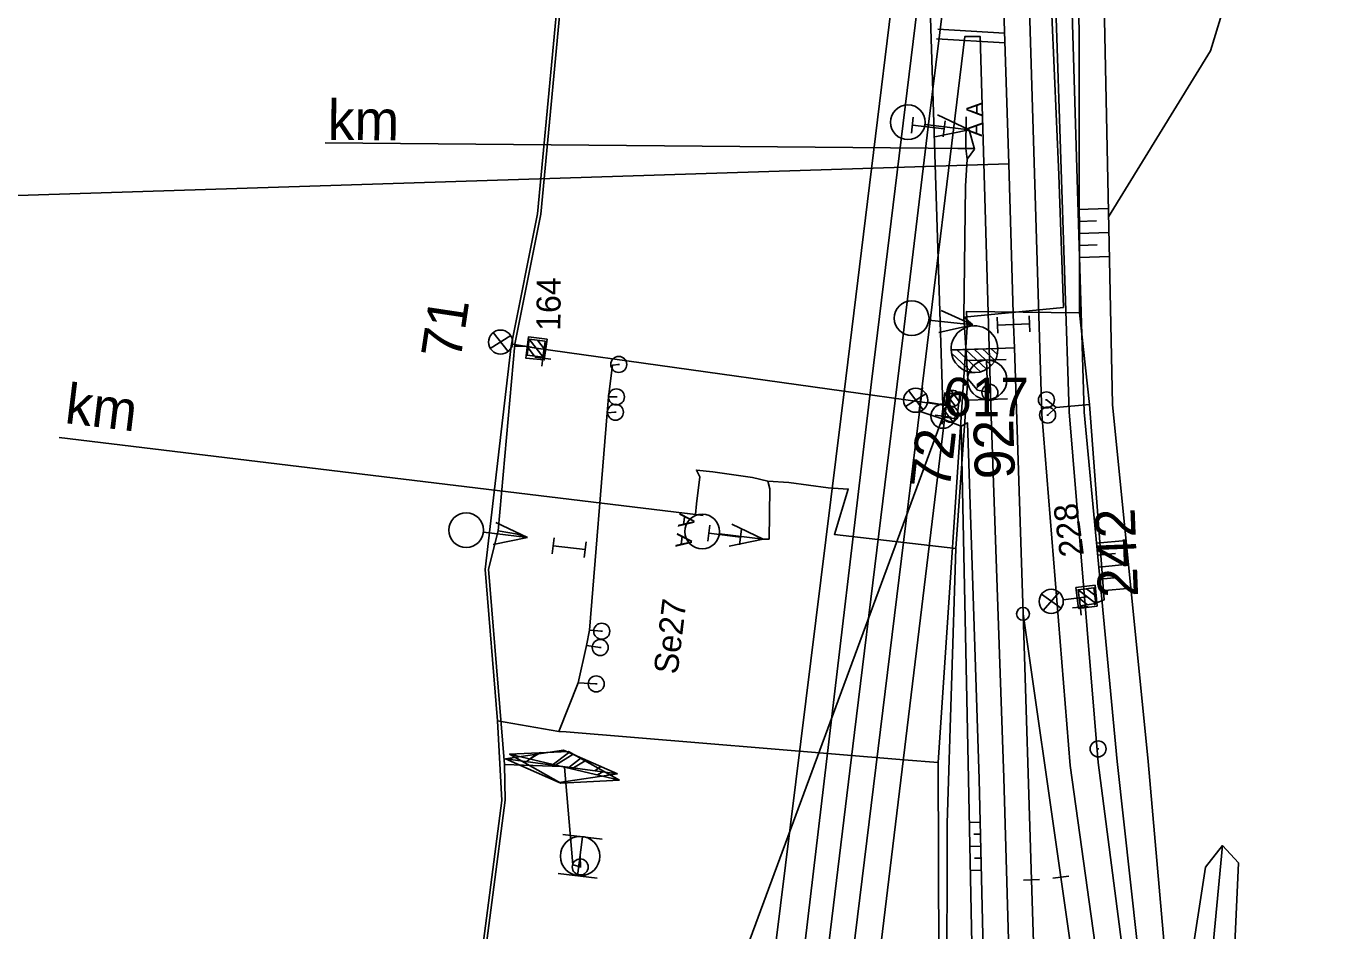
# Model space of a CAD drawing. Extents: x -598638 to -597933, y -1164002 to -1161904.
# Drawn here: x -598566.1 to -598484.7, y -1163411 to -1163354.5 of the extents above; entities that cross this region are included whole.
import ezdxf

# ---------------------------------------------------------------- set-up
doc = ezdxf.new("R2010")
doc.units = 0
for name, color, linetype in [('Vrstva 1', 7, 'Continuous'), ('Vrstva 11', 7, 'Continuous'), ('Vrstva 12', 7, 'Continuous'), ('Vrstva 13', 7, 'Continuous'), ('Vrstva 2', 7, 'Continuous'), ('Vrstva 25', 7, 'Continuous'), ('Vrstva 26', 7, 'Continuous'), ('Vrstva 28', 7, 'Continuous'), ('Vrstva 3', 7, 'Continuous'), ('Vrstva 31', 7, 'Continuous'), ('Vrstva 35', 7, 'Continuous'), ('Vrstva 4', 7, 'Continuous'), ('Vrstva 48', 7, 'Continuous'), ('Vrstva 49', 7, 'Continuous'), ('Vrstva 51', 7, 'Continuous'), ('Vrstva 6', 7, 'Continuous'), ('Vrstva 63', 7, 'Continuous'), ('Vrstva 7', 7, 'Continuous')]:
    doc.layers.add(name, color=color, linetype=linetype)

msp = doc.modelspace()

# ---------------------------------------------------------------- linework, layer by layer
at = {"layer": 'Vrstva 1'}
msp.add_line((-598504.722, -1163363.13), (-598604.671, -1163366.323), dxfattribs=at)
for points in [[(-598540.061, -1163609.51), (-598538.55, -1163597.18), (-598535.661, -1163573.393), (-598532.502, -1163547.551), (-598529.47, -1163522.734), (-598526.451, -1163497.915), (-598523.419, -1163473.102), (-598521.347, -1163456.074), (-598520.4, -1163448.28), (-598517.374, -1163423.469), (-598514.348, -1163398.653), (-598511.323, -1163373.834), (-598509.75, -1163360.838), (-598508.294, -1163349.021), (-598507.057, -1163338.802)], [(-598504.357, -1163374.632), (-598504.42, -1163373.167), (-598504.722, -1163363.13), (-598505.089, -1163351.642)], [(-598503.303, -1163407.847), (-598503.83, -1163391.239), (-598504.357, -1163374.632)], [(-598501.472, -1163407.683), (-598503.83, -1163391.239)], [(-598502.896, -1163420.949), (-598503.303, -1163407.847)], [(-598499.762, -1163419.602), (-598501.472, -1163407.683)]]:
    msp.add_lwpolyline(points, dxfattribs=at)
at = {"layer": 'Vrstva 11'}
for p, q in [((-598534.327, -1163375.142), (-598534.73, -1163374.619)), ((-598533.801, -1163375.209), (-598534.662, -1163374.093)), ((-598533.731, -1163374.687), (-598534.139, -1163374.158)), ((-598508.658, -1163377.504), (-598508.077, -1163378.253)), ((-598508.345, -1163377.295), (-598507.798, -1163378)), ((-598508.785, -1163378.499), (-598508.205, -1163379.246)), ((-598508.473, -1163378.289), (-598507.924, -1163378.996)), ((-598499.283, -1163390.602), (-598500.4, -1163389.741)), ((-598499.809, -1163390.67), (-598500.332, -1163390.267)), ((-598499.348, -1163390.079), (-598499.877, -1163389.671))]:
    msp.add_line(p, q, dxfattribs=at)
for points in [[(-598534.79, -1163375.082), (-598534.662, -1163374.09), (-598533.67, -1163374.218), (-598533.798, -1163375.21)], [(-598500.272, -1163390.73), (-598500.4, -1163389.738), (-598499.408, -1163389.61), (-598499.28, -1163390.602)]]:
    msp.add_lwpolyline(points, close=True, dxfattribs=at)
for points in [[(-598534.79, -1163375.082), (-598534.662, -1163374.09), (-598533.67, -1163374.218), (-598533.798, -1163375.21), (-598534.79, -1163375.082)], [(-598534.23, -1163374.65), (-598508.31, -1163378.28)], [(-598500.272, -1163390.73), (-598500.4, -1163389.738), (-598499.408, -1163389.61), (-598499.28, -1163390.602), (-598500.272, -1163390.73)]]:
    msp.add_lwpolyline(points, dxfattribs=at)
for centre in [(-598508.248, -1163377.784), (-598508.248, -1163377.784), (-598508.372, -1163378.776), (-598508.372, -1163378.776)]:
    msp.add_circle(centre, 0.5, dxfattribs=at)
at = {"layer": 'Vrstva 12'}
for p, q in [((-598499.32, -1163389.44), (-598499.2, -1163390.75)), ((-598500.53, -1163389.6), (-598500.36, -1163390.9)), ((-598499.2, -1163390.75), (-598500.36, -1163390.9))]:
    msp.add_line(p, q, dxfattribs=at)
for points in [[(-598533.55, -1163374.08), (-598533.72, -1163375.38), (-598534.88, -1163375.27), (-598534.71, -1163373.95), (-598533.55, -1163374.08)], [(-598508.9, -1163378.94), (-598508.71, -1163377.43), (-598507.77, -1163377.55), (-598507.96, -1163379.06), (-598508.9, -1163378.94)], [(-598500.53, -1163389.6), (-598499.32, -1163389.44)]]:
    msp.add_lwpolyline(points, dxfattribs=at)
at = {"layer": 'Vrstva 13'}
for points in [[(-598494.35, -1163419.483), (-598496.011, -1163400.454), (-598498.249, -1163378.174), (-598498.761, -1163353.124), (-598499.609, -1163337.312), (-598498.929, -1163312.944), (-598495.877, -1163288.306), (-598493.588, -1163272.056)], [(-598496.865, -1163550.379), (-598493.505, -1163528.163), (-598490.621, -1163501.64), (-598489.924, -1163482.727), (-598490.976, -1163458.949), (-598491.652, -1163439.005), (-598492.756, -1163420.248), (-598491.376, -1163405.706)]]:
    msp.add_lwpolyline(points, dxfattribs=at)
at = {"layer": 'Vrstva 2'}
for p, q in [((-598508.321, -1163374.76), (-598505.395, -1163374.668)), ((-598508.321, -1163374.761), (-598508.321, -1163374.76)), ((-598508.318, -1163374.769), (-598504.357, -1163374.632)), ((-598506.495, -1163376.128), (-598507.964, -1163374.748)), ((-598506.11, -1163375.968), (-598507.427, -1163374.731)), ((-598505.809, -1163375.729), (-598506.89, -1163374.714)), ((-598505.581, -1163375.423), (-598506.353, -1163374.698)), ((-598505.434, -1163375.039), (-598505.815, -1163374.681)), ((-598507.008, -1163376.168), (-598508.299, -1163374.956)), ((-598503.803, -1163407.863), (-598502.803, -1163407.831)), ((-598501.967, -1163407.754), (-598500.977, -1163407.612))]:
    msp.add_line(p, q, dxfattribs=at)
for points in [[(-598503.303, -1163407.847), (-598503.83, -1163391.239), (-598504.357, -1163374.632)], [(-598501.472, -1163407.683), (-598503.83, -1163391.239)]]:
    msp.add_lwpolyline(points, dxfattribs=at)
msp.add_circle((-598503.836, -1163391.239), 0.4, dxfattribs=at)
for centre, radius, start, end in [((-598506.863, -1163374.714), 1.462, 1.74804, 182.21756), ((-598506.863, -1163374.715), 1.464, 181.83757, 1.79842)]:
    msp.add_arc(centre, radius, start, end, dxfattribs=at)
at = {"layer": 'Vrstva 25'}
for p, q in [((-598537.092, -1163374.668), (-598535.815, -1163373.868)), ((-598536.907, -1163373.67), (-598535.985, -1163374.864)), ((-598535.709, -1163374.399), (-598534.23, -1163374.65)), ((-598529.122, -1163375.664), (-598529.022, -1163375.664)), ((-598529.271, -1163377.692), (-598529.171, -1163377.692)), ((-598511.172, -1163378.298), (-598509.895, -1163377.498)), ((-598510.987, -1163377.3), (-598510.065, -1163378.494)), ((-598509.789, -1163378.029), (-598508.31, -1163378.28)), ((-598505.95, -1163377.41), (-598505.85, -1163377.41)), ((-598502.419, -1163377.879), (-598502.319, -1163377.879)), ((-598529.331, -1163378.646), (-598529.231, -1163378.646)), ((-598502.346, -1163378.825), (-598502.246, -1163378.825)), ((-598502.687, -1163390.019), (-598501.455, -1163390.89)), ((-598502.571, -1163391.027), (-598501.584, -1163389.888)), ((-598501.327, -1163390.364), (-598499.84, -1163390.17)), ((-598530.187, -1163392.327), (-598530.087, -1163392.327)), ((-598530.279, -1163393.34), (-598530.179, -1163393.34)), ((-598530.531, -1163395.616), (-598530.431, -1163395.616)), ((-598531.52, -1163407.04), (-598531.42, -1163407.04))]:
    msp.add_line(p, q, dxfattribs=at)
for centre, radius in [((-598536.452, -1163374.271), 0.754), ((-598529.072, -1163375.664), 0.5), ((-598529.221, -1163377.692), 0.5), ((-598510.532, -1163377.901), 0.754), ((-598505.899, -1163377.416), 0.5), ((-598502.369, -1163377.879), 0.5), ((-598529.281, -1163378.646), 0.5), ((-598502.296, -1163378.825), 0.5), ((-598502.075, -1163390.46), 0.754), ((-598530.137, -1163392.327), 0.5), ((-598530.229, -1163393.34), 0.5), ((-598530.481, -1163395.616), 0.5), ((-598531.478, -1163407.046), 0.5)]:
    msp.add_circle(centre, radius, dxfattribs=at)
at = {"layer": 'Vrstva 26'}
for points in [[(-598498.151, -1163310.108), (-598499.599, -1163328.429), (-598500.358, -1163348.412), (-598500.307, -1163372.443), (-598499.677, -1163378.168), (-598498.772, -1163390.367), (-598499.181, -1163390.54), (-598499.381, -1163390.672)], [(-598537.412, -1163388.462), (-598535.789, -1163374.512), (-598534.155, -1163366.253), (-598531.883, -1163342.146), (-598532.145, -1163325.87), (-598528.971, -1163314.666)], [(-598507.316, -1163373.338), (-598507.371, -1163372.367), (-598500.307, -1163372.443)], [(-598507.316, -1163373.338), (-598509.135, -1163400.512)], [(-598535.533, -1163374.519), (-598534.909, -1163374.528), (-598534.527, -1163374.59)], [(-598532.805, -1163398.581), (-598531.604, -1163395.54), (-598531.09, -1163393.218), (-598530.889, -1163392.255), (-598529.802, -1163378.681), (-598529.704, -1163377.682), (-598529.471, -1163375.716), (-598529.072, -1163375.664)], [(-598529.704, -1163377.682), (-598529.221, -1163377.692)], [(-598501.756, -1163378.345), (-598502.369, -1163377.879)], [(-598529.802, -1163378.681), (-598529.281, -1163378.646)], [(-598499.677, -1163378.168), (-598501.756, -1163378.345), (-598502.296, -1163378.825)], [(-598545.332, -1163489.631), (-598545.008, -1163488.013), (-598544.032, -1163482.82), (-598544.736, -1163479.954), (-598543.755, -1163474.998), (-598543.294, -1163474.254), (-598542.12, -1163472.372), (-598541.435, -1163468.483), (-598542.191, -1163467.82), (-598543.3, -1163466.865), (-598549.702, -1163463.438), (-598550.312, -1163461.998), (-598547.972, -1163456.485), (-598545.109, -1163451.121), (-598540.175, -1163430.965), (-598539.287, -1163425.257), (-598536.381, -1163402.898), (-598536.647, -1163397.91), (-598537.412, -1163388.462)], [(-598530.889, -1163392.255), (-598530.137, -1163392.327)], [(-598531.09, -1163393.218), (-598530.229, -1163393.34)], [(-598531.604, -1163395.54), (-598530.481, -1163395.616)], [(-598509.054, -1163424.983), (-598509.135, -1163400.512), (-598511.269, -1163400.35), (-598532.35, -1163398.602), (-598532.805, -1163398.581), (-598536.647, -1163397.91)]]:
    msp.add_lwpolyline(points, dxfattribs=at)
at = {"layer": 'Vrstva 28'}
for points in [[(-598507.52, -1163372.71), (-598501.31, -1163372.1), (-598501.6, -1163363.82), (-598502.03, -1163353.84), (-598501.69, -1163351.72), (-598500.63, -1163349.09), (-598500.75, -1163347.83), (-598501.57, -1163344.03), (-598502, -1163332.02), (-598501.94, -1163329.98), (-598501.12, -1163326.18), (-598499.72, -1163322.54), (-598499.97, -1163317.56), (-598499.92, -1163312.46), (-598499.63, -1163308.85), (-598499.29, -1163304.55), (-598499.04, -1163301.37), (-598499.81, -1163300.75), (-598504.99, -1163300.1), (-598505.15, -1163303.01), (-598505.18, -1163303.79)], [(-598528.804, -1163314.884), (-598530.72, -1163322.93), (-598531.923, -1163325.895), (-598531.661, -1163342.171), (-598533.933, -1163366.278), (-598535.552, -1163374.399), (-598536.6, -1163386.06), (-598535.39, -1163386.27), (-598534.78, -1163386.47)], [(-598514.7, -1163462.74), (-598512.83, -1163458.19), (-598512.34, -1163456.24), (-598510.26, -1163440.38), (-598509.64, -1163435.49), (-598509.26, -1163430.59), (-598508.84, -1163423.22), (-598508.68, -1163420.47), (-598508.59, -1163415.6), (-598508.57, -1163404.31), (-598508.02, -1163387.15), (-598507.28, -1163376.57), (-598507.52, -1163372.71), (-598507.43, -1163364.54), (-598507.33, -1163362.84), (-598506.87, -1163362.23), (-598507.2, -1163361.02)], [(-598507.33, -1163362.84), (-598507.4, -1163362.18)], [(-598507.52, -1163372.71), (-598506.96, -1163373.2)], [(-598507.28, -1163376.57), (-598506.67, -1163377.27), (-598505.9, -1163377.41), (-598506.07, -1163376.62)], [(-598508.02, -1163387.15), (-598515.61, -1163386.28), (-598514.74, -1163383.45), (-598515.99, -1163383.38), (-598518.45, -1163383.04), (-598519.76, -1163382.96), (-598520.73, -1163382.72), (-598523.2, -1163382.38), (-598524.22, -1163382.26), (-598524.01, -1163382.69), (-598524.21, -1163384.36), (-598524.29, -1163385.04)], [(-598519.76, -1163382.96), (-598519.63, -1163383.44), (-598519.69, -1163386.57), (-598520.05, -1163386.57)], [(-598536.6, -1163386.06), (-598537.199, -1163388.446), (-598536.213, -1163400.645), (-598532.653, -1163400.768), (-598532.455, -1163400.815), (-598531.93, -1163406.91), (-598531.47, -1163407.04), (-598531.49, -1163406.38)], [(-598536.213, -1163400.645), (-598536.168, -1163402.882), (-598539.241, -1163426.522), (-598539.962, -1163430.949), (-598541.59, -1163438.158), (-598542.388, -1163441.691), (-598544.896, -1163451.105), (-598547.759, -1163456.469), (-598550.099, -1163461.982), (-598549.524, -1163463.34), (-598543.087, -1163466.786), (-598541.213, -1163468.412), (-598540.83, -1163467.6), (-598540.45, -1163467.34), (-598539.56, -1163463.45), (-598538.42, -1163453.46), (-598538.38, -1163452.75)]]:
    msp.add_lwpolyline(points, dxfattribs=at)
at = {"layer": 'Vrstva 3'}
for p, q in [((-598507.2, -1163361.02), (-598509.17, -1163360.082)), ((-598510.803, -1163361.213), (-598510.682, -1163360.22)), ((-598510.743, -1163360.717), (-598508.757, -1163360.959)), ((-598507.2, -1163361.02), (-598509.939, -1163360.682)), ((-598508.818, -1163361.456), (-598508.697, -1163360.463)), ((-598507.2, -1163361.02), (-598509.339, -1163361.452)), ((-598506.96, -1163373.2), (-598508.944, -1163372.292)), ((-598506.96, -1163373.2), (-598509.704, -1163372.903)), ((-598506.96, -1163373.2), (-598509.092, -1163373.664)), ((-598505.401, -1163373.703), (-598505.438, -1163372.704)), ((-598505.419, -1163373.204), (-598503.421, -1163373.13)), ((-598503.402, -1163373.63), (-598503.439, -1163372.631)), ((-598507.34, -1163375.428), (-598504.878, -1163375.35)), ((-598506.031, -1163377.851), (-598506.109, -1163375.389)), ((-598507.262, -1163377.89), (-598504.8, -1163377.812)), ((-598534.78, -1163386.47), (-598537.52, -1163386.136)), ((-598534.78, -1163386.47), (-598536.751, -1163385.535)), ((-598523.513, -1163386.695), (-598523.392, -1163385.703)), ((-598523.453, -1163386.199), (-598521.467, -1163386.441)), ((-598520.05, -1163386.57), (-598522.021, -1163385.635)), ((-598521.528, -1163386.937), (-598521.407, -1163385.945)), ((-598534.78, -1163386.47), (-598536.918, -1163386.904)), ((-598533.223, -1163387.485), (-598533.102, -1163386.493)), ((-598533.163, -1163386.989), (-598531.177, -1163387.231)), ((-598531.238, -1163387.727), (-598531.117, -1163386.735)), ((-598520.05, -1163386.57), (-598522.79, -1163386.236)), ((-598520.05, -1163386.57), (-598522.188, -1163387.004)), ((-598532.564, -1163405.008), (-598530.118, -1163405.306)), ((-598531.639, -1163407.603), (-598531.341, -1163405.157)), ((-598532.862, -1163407.454), (-598530.416, -1163407.752))]:
    msp.add_line(p, q, dxfattribs=at)
for centre, radius in [((-598511.018, -1163360.544), 1.084), ((-598510.786, -1163372.78), 1.084), ((-598506.068, -1163376.618), 1.232), ((-598538.598, -1163386.012), 1.084), ((-598523.86, -1163386.101), 1.084), ((-598531.485, -1163406.369), 1.232)]:
    msp.add_circle(centre, radius, dxfattribs=at)
at = {"layer": 'Vrstva 31'}
for p, q in [((-598535.472, -1163399.986), (-598535.602, -1163400.068)), ((-598534.239, -1163400.004), (-598534.851, -1163400.472)), ((-598533.957, -1163399.897), (-598534.612, -1163400.303)), ((-598532.209, -1163399.912), (-598533.231, -1163400.69)), ((-598531.928, -1163400.007), (-598533.022, -1163400.68)), ((-598535.738, -1163400.242), (-598535.858, -1163400.337)), ((-598531.41, -1163400.239), (-598532.186, -1163400.831)), ((-598531.165, -1163400.412), (-598531.996, -1163400.924)), ((-598530.198, -1163400.77), (-598530.563, -1163401.049)), ((-598530.012, -1163401.06), (-598530.403, -1163401.302)), ((-598529.439, -1163401.128), (-598529.554, -1163401.185)), ((-598529.292, -1163401.492), (-598529.413, -1163401.537))]:
    msp.add_line(p, q, dxfattribs=at)
for points in [[(-598523.305, -1163315.147), (-598528.804, -1163314.884), (-598530.72, -1163322.93), (-598531.923, -1163325.895), (-598531.661, -1163342.171), (-598533.933, -1163366.278), (-598535.552, -1163374.399), (-598536.6, -1163386.06), (-598537.199, -1163388.446)], [(-598537.199, -1163388.446), (-598536.213, -1163400.645), (-598536.168, -1163402.882), (-598539.241, -1163426.522), (-598539.962, -1163430.949), (-598541.59, -1163438.158), (-598542.388, -1163441.691), (-598544.896, -1163451.105), (-598547.759, -1163456.469), (-598550.099, -1163461.982), (-598549.524, -1163463.34), (-598543.087, -1163466.786), (-598541.213, -1163468.412), (-598541.912, -1163472.382), (-598543.54, -1163474.971), (-598544.53, -1163479.976), (-598543.818, -1163482.855), (-598547.027, -1163483.149)], [(-598529.026, -1163401.629), (-598532.69, -1163401.805), (-598535.884, -1163400.001)], [(-598532.455, -1163400.815), (-598532.653, -1163400.768), (-598536.213, -1163400.645)], [(-598529.161, -1163401.238), (-598532.789, -1163401.777), (-598536.146, -1163400.298)]]:
    msp.add_lwpolyline(points, dxfattribs=at)
for points in [[(-598529.161, -1163401.238), (-598532.518, -1163399.759), (-598536.146, -1163400.298)], [(-598529.026, -1163401.629), (-598532.22, -1163399.825), (-598535.884, -1163400.001)]]:
    msp.add_lwpolyline(points, close=True, dxfattribs=at)
at = {"layer": 'Vrstva 35'}
for points in [[(-598514.74, -1163383.45), (-598515.99, -1163383.38), (-598518.45, -1163383.04), (-598519.76, -1163382.96), (-598520.73, -1163382.72), (-598523.2, -1163382.38), (-598524.22, -1163382.26)], [(-598508.02, -1163387.15), (-598515.61, -1163386.28)]]:
    msp.add_lwpolyline(points, dxfattribs=at)
at = {"layer": 'Vrstva 4'}
msp.add_lwpolyline([(-598497.798, -1163553.336), (-598494.995, -1163527.601), (-598492.818, -1163506.812), (-598492.18, -1163480.33), (-598492.913, -1163450.825), (-598495.032, -1163426.834), (-598497.953, -1163400.465), (-598500.02, -1163378.635), (-598500.795, -1163353.032), (-598500.992, -1163338.686), (-598498.929, -1163312.944)], dxfattribs=at)
at = {"layer": 'Vrstva 48'}
for p, q in [((-598498.499, -1163365.922), (-598500.403, -1163365.98)), ((-598499.243, -1163366.695), (-598500.38, -1163366.729)), ((-598498.469, -1163367.422), (-598500.358, -1163367.479)), ((-598499.206, -1163368.194), (-598500.335, -1163368.229)), ((-598498.438, -1163368.921), (-598500.312, -1163368.978)), ((-598497.398, -1163386.651), (-598499.244, -1163386.826)), ((-598498.063, -1163387.467), (-598499.174, -1163387.572)), ((-598497.248, -1163388.143), (-598499.103, -1163388.319)), ((-598497.917, -1163388.96), (-598499.032, -1163389.066)), ((-598497.098, -1163389.636), (-598498.962, -1163389.812)), ((-598507.186, -1163404.261), (-598506.514, -1163404.245)), ((-598507.155, -1163405.76), (-598506.478, -1163405.744)), ((-598506.901, -1163405.004), (-598506.496, -1163404.994)), ((-598506.868, -1163406.504), (-598506.46, -1163406.494)), ((-598507.125, -1163407.26), (-598506.442, -1163407.244))]:
    msp.add_line(p, q, dxfattribs=at)
at = {"layer": 'Vrstva 49'}
for points in [[(-598391.197, -1163180.19), (-598395.305, -1163187.937), (-598394.98, -1163196.89), (-598419.634, -1163238.873), (-598429.644, -1163245.8), (-598443.382, -1163271.777), (-598461.098, -1163296.975), (-598474.043, -1163315.865), (-598479.917, -1163316.087), (-598492.118, -1163356.078), (-598498.501, -1163366.442)], [(-598533.45, -1163670.11), (-598536.816, -1163665.931), (-598535.031, -1163653.367), (-598531.766, -1163626.047), (-598527.127, -1163591.782), (-598522.536, -1163563.12), (-598519.726, -1163549.297), (-598516.46, -1163523.044), (-598514.479, -1163505.41), (-598510.834, -1163479.337), (-598507.262, -1163450.223), (-598506.719, -1163427.295), (-598507.24, -1163401.571), (-598507.685, -1163379.523)], [(-598497.798, -1163553.336), (-598494.93, -1163550.871), (-598491.112, -1163528.455), (-598487.512, -1163502.102), (-598487.008, -1163482.722), (-598488.866, -1163459.174), (-598489.773, -1163438.794), (-598491.024, -1163421.023), (-598490.384, -1163406.778), (-598491.376, -1163405.706), (-598492.434, -1163407.048), (-598494.35, -1163419.483)]]:
    msp.add_lwpolyline(points, dxfattribs=at)
at = {"layer": 'Vrstva 51'}
for points in [[(-598501.352, -1163557.294), (-598497.322, -1163527.011), (-598495.22, -1163506.407), (-598494.37, -1163480.26), (-598495.305, -1163450.791), (-598497.315, -1163426.39), (-598500.887, -1163400.701), (-598502.656, -1163378.776), (-598503.412, -1163354.17), (-598503.666, -1163338.931), (-598502.177, -1163312.329), (-598499.265, -1163287.777)], [(-598497.685, -1163287.962), (-598500.382, -1163312.707), (-598501.939, -1163338.79), (-598501.766, -1163354.027), (-598500.944, -1163378.633), (-598499.148, -1163400.517), (-598495.815, -1163426.176), (-598493.871, -1163450.799), (-598492.924, -1163480.338), (-598493.516, -1163506.634), (-598495.537, -1163527.526), (-598499.905, -1163557.48), (-598501.352, -1163557.294)], [(-598538.768, -1163586.309), (-598539.802, -1163586.224), (-598538.809, -1163572.569), (-598537.239, -1163559.929), (-598532.111, -1163517.921), (-598526.717, -1163473.944), (-598521.465, -1163429.602), (-598514.887, -1163376.546), (-598510.204, -1163338.254)], [(-598538.768, -1163586.309), (-598535.642, -1163560.269), (-598530.513, -1163518.107), (-598525.128, -1163474.169), (-598519.579, -1163429.781), (-598513.288, -1163376.745), (-598508.587, -1163338.31)], [(-598534.658, -1163696.543), (-598531.502, -1163671.551), (-598529.287, -1163653.433), (-598525.975, -1163626.57), (-598521.938, -1163592.563), (-598518.465, -1163564.479), (-598513.549, -1163524.372), (-598511.098, -1163505.278), (-598507.979, -1163479.625), (-598504.96, -1163450.403), (-598504.276, -1163427.476), (-598505.025, -1163401.487), (-598505.825, -1163378.899), (-598506.504, -1163355.19), (-598507.471, -1163355.188), (-598510.311, -1163378.58), (-598508.823, -1163379.075)], [(-598576.024, -1163916.782), (-598567.765, -1163849.248), (-598562.666, -1163807.337), (-598557.481, -1163765.121), (-598551.011, -1163711.819), (-598545.358, -1163665.341), (-598539.95, -1163621.544), (-598532.519, -1163560.697), (-598527.374, -1163518.619), (-598522.03, -1163474.673), (-598516.65, -1163430.324), (-598510.109, -1163377.102)], [(-598574.157, -1163917.019), (-598566.089, -1163849.397), (-598561.002, -1163807.966), (-598555.82, -1163765.416), (-598552.514, -1163737.416), (-598552.899, -1163737.337), (-598549.975, -1163711.888), (-598548.115, -1163696.332), (-598547.607, -1163696.337), (-598543.685, -1163665.616), (-598538.398, -1163621.635), (-598530.925, -1163561.125), (-598525.708, -1163519.023), (-598520.47, -1163474.952), (-598514.977, -1163430.656), (-598508.517, -1163377.394)], [(-598534.658, -1163696.543), (-598536.237, -1163696.276), (-598532.874, -1163671.321), (-598530.993, -1163653.169), (-598527.57, -1163626.458), (-598523.511, -1163592.285), (-598520.081, -1163564.257), (-598518.332, -1163549.644), (-598515.065, -1163524.058), (-598512.806, -1163504.945), (-598509.548, -1163479.335), (-598506.49, -1163450.359), (-598505.964, -1163427.237), (-598506.578, -1163401.572), (-598507.29, -1163379.316), (-598507.685, -1163379.523), (-598508.823, -1163379.075)]]:
    msp.add_lwpolyline(points, dxfattribs=at)
at = {"layer": 'Vrstva 6'}
for p, q in [((-598507.383, -1163360.2), (-598507.4, -1163362.18)), ((-598547.399, -1163361.818), (-598507.4, -1163362.18)), ((-598507.899, -1163362.176), (-598506.901, -1163362.184)), ((-598564.001, -1163380.233), (-598524.29, -1163385.04)), ((-598524.787, -1163384.98), (-598523.794, -1163385.101))]:
    msp.add_line(p, q, dxfattribs=at)
at = {"layer": 'Vrstva 63'}
for p, q in [((-598508.824, -1163378.896), (-598513.197, -1163240.04)), ((-598539.744, -1163462.649), (-598508.824, -1163378.896)), ((-598508.874, -1163378.896), (-598508.774, -1163378.896))]:
    msp.add_line(p, q, dxfattribs=at)
msp.add_circle((-598508.824, -1163378.896), 0.756, dxfattribs=at)
at = {"layer": 'Vrstva 7'}
for p, q in [((-598504.982, -1163354.979), (-598509.152, -1163354.738)), ((-598504.963, -1163355.581), (-598509.241, -1163355.334)), ((-598533.752, -1163374.775), (-598533.876, -1163375.767)), ((-598533.318, -1163375.333), (-598534.31, -1163375.209)), ((-598508.327, -1163378.954), (-598509.321, -1163378.838)), ((-598508.766, -1163378.399), (-598508.882, -1163379.393)), ((-598500.754, -1163390.873), (-598499.758, -1163390.783)), ((-598500.301, -1163390.33), (-598500.211, -1163391.326)), ((-598499.192, -1163399.669), (-598499.092, -1163399.669))]:
    msp.add_line(p, q, dxfattribs=at)
msp.add_circle((-598499.142, -1163399.669), 0.5, dxfattribs=at)

# ---------------------------------------------------------------- texts
at = {"layer": 'Vrstva 11'}
for s, rotation, p in [('71', 81.42333, (-598538.959, -1163375.425)), ('72', 83.57125, (-598508.419, -1163383.533)), ('242', 92.29034, (-598496.642, -1163390.17))]:
    msp.add_text(s, height=2.5, rotation=rotation, dxfattribs=at).set_placement(p)
at = {"layer": 'Vrstva 2'}
msp.add_text('92', height=2.5, rotation=91.81751, dxfattribs=at).set_placement((-598504.33, -1163382.786))
at = {"layer": 'Vrstva 25'}
for s, rotation, p in [('164', 89.57231, (-598532.716, -1163373.573)), ('228', 97.45016, (-598500.025, -1163387.574))]:
    msp.add_text(s, height=1.5, rotation=rotation, dxfattribs=at).set_placement(p)
at = {"layer": 'Vrstva 6'}
for s, height, rotation, p in [('km ', 2.5, 359.48172, (-598547.25, -1163361.64)), ('  A A', 1, 89.48172, (-598506.4, -1163362.189)), ('km ', 2.5, 353.09704, (-598563.718, -1163379.32)), ('A A', 1, 263.09704, (-598525.283, -1163384.92)), ('Se27', 1.5, 83.09704, (-598525.406, -1163395.058))]:
    msp.add_text(s, height=height, rotation=rotation, dxfattribs=at).set_placement(p)
at = {"layer": 'Vrstva 63'}
msp.add_text('617', height=2.4, dxfattribs=at).set_placement((-598508.824, -1163378.896))

doc.saveas('drawing.dxf')
